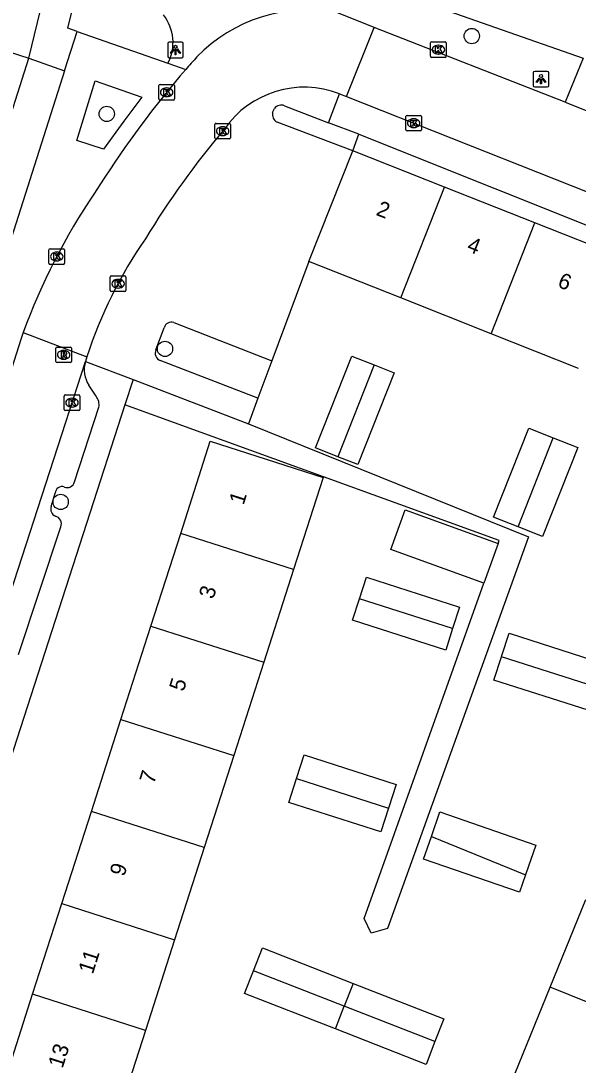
# Model space of a CAD drawing. Extents: x 162812 to 163818, y 381639 to 382470.
# Drawn here: x 163241.1 to 163276.7, y 382068.4 to 382135.2 of the extents above; entities that cross this region are included whole.
import ezdxf

# ---------------------------------------------------------------- set-up
doc = ezdxf.new("R2010")
doc.units = 0
for name, color, linetype in [('IMGEO_Boom', 7, 'Continuous'), ('IMGEO_Groenvoorziening', 7, 'Continuous'), ('IMGEO_Kolk', 7, 'Continuous'), ('IMGEO_Lichtpunt', 7, 'Continuous'), ('IMGEO_Pand', 7, 'Continuous'), ('IMGEO_Pand_nummerreeks', 7, 'Continuous'), ('IMGEO_Parkeervlak_open', 7, 'Continuous'), ('IMGEO_Rijbaan_lokaal_open', 7, 'Continuous'), ('IMGEO_Rioolput', 7, 'Continuous'), ('IMGEO_Voetpad_open', 7, 'Continuous')]:
    doc.layers.add(name, color=color, linetype=linetype)

msp = doc.modelspace()

# ---------------------------------------------------------------- linework, layer by layer
at = {"layer": 'IMGEO_Boom'}
for centre in [(163269.925, 382134.237), (163246.606, 382129.258), (163250.325, 382114.233), (163243.659, 382104.451)]:
    msp.add_circle(centre, 0.489, dxfattribs=at)
at = {"layer": 'IMGEO_Groenvoorziening'}
for points in [[(163262.321, 382126.907), (163262.701, 382127.953)], [(163257.147, 382113.465), (163256.257, 382111.077)]]:
    msp.add_lwpolyline(points, dxfattribs=at)
at = {"layer": 'IMGEO_Kolk'}
for p, q in [((163267.295, 382132.939), (163267.295, 382133.791)), ((163267.37, 382133.865), (163268.222, 382133.865)), ((163267.783, 382133.645), (163267.808, 382133.645)), ((163268.296, 382133.791), (163268.296, 382132.939)), ((163268.222, 382132.865), (163267.37, 382132.865)), ((163267.806, 382133.085), (163267.781, 382133.085)), ((163249.933, 382130.216), (163249.933, 382131.068)), ((163250.008, 382131.142), (163250.86, 382131.142)), ((163250.421, 382130.922), (163250.446, 382130.922)), ((163250.934, 382131.068), (163250.934, 382130.216)), ((163250.86, 382130.142), (163250.008, 382130.142)), ((163250.444, 382130.362), (163250.419, 382130.362)), ((163253.585, 382128.655), (163254.437, 382128.655)), ((163265.715, 382128.24), (163265.715, 382129.092)), ((163265.79, 382129.166), (163266.642, 382129.166)), ((163266.203, 382128.946), (163266.228, 382128.946)), ((163266.716, 382129.092), (163266.716, 382128.24)), ((163253.51, 382127.729), (163253.51, 382128.581)), ((163253.998, 382128.435), (163254.023, 382128.435)), ((163254.511, 382128.581), (163254.511, 382127.729)), ((163266.642, 382128.166), (163265.79, 382128.166)), ((163266.226, 382128.386), (163266.201, 382128.386)), ((163254.437, 382127.655), (163253.585, 382127.655)), ((163254.021, 382127.875), (163253.996, 382127.875)), ((163242.986, 382120.64), (163243.838, 382120.64)), ((163242.911, 382119.714), (163242.911, 382120.566)), ((163243.399, 382120.42), (163243.424, 382120.42)), ((163243.912, 382120.566), (163243.912, 382119.714)), ((163243.838, 382119.64), (163242.986, 382119.64)), ((163243.422, 382119.86), (163243.397, 382119.86)), ((163246.83, 382117.975), (163246.83, 382118.827)), ((163246.905, 382118.901), (163247.757, 382118.901)), ((163247.318, 382118.681), (163247.343, 382118.681)), ((163247.831, 382118.827), (163247.831, 382117.975)), ((163247.341, 382118.121), (163247.316, 382118.121)), ((163247.757, 382117.901), (163246.905, 382117.901)), ((163243.961, 382111.295), (163244.813, 382111.295)), ((163243.886, 382110.369), (163243.886, 382111.221)), ((163244.374, 382111.075), (163244.399, 382111.075)), ((163244.887, 382111.221), (163244.887, 382110.369)), ((163244.813, 382110.295), (163243.961, 382110.295)), ((163244.397, 382110.515), (163244.372, 382110.515))]:
    msp.add_line(p, q, dxfattribs=at)
for points in [[(163267.295, 382132.939), (163267.295, 382133.791)], [(163267.37, 382133.865), (163268.222, 382133.865)], [(163267.616, 382133.565), (163267.739, 382133.565), (163267.739, 382133.414), (163267.869, 382133.565), (163268.033, 382133.565), (163267.887, 382133.414), (163268.04, 382133.165), (163267.888, 382133.165), (163267.803, 382133.329), (163267.739, 382133.262), (163267.739, 382133.165), (163267.616, 382133.165), (163267.616, 382133.565)], [(163268.296, 382133.791), (163268.296, 382132.939)], [(163268.222, 382132.865), (163267.37, 382132.865)], [(163249.933, 382130.216), (163249.933, 382131.068)], [(163250.008, 382131.142), (163250.86, 382131.142)], [(163250.254, 382130.842), (163250.377, 382130.842), (163250.377, 382130.691), (163250.507, 382130.842), (163250.671, 382130.842), (163250.525, 382130.691), (163250.678, 382130.442), (163250.526, 382130.442), (163250.441, 382130.606), (163250.377, 382130.539), (163250.377, 382130.442), (163250.254, 382130.442), (163250.254, 382130.842)], [(163250.934, 382131.068), (163250.934, 382130.216)], [(163250.86, 382130.142), (163250.008, 382130.142)], [(163253.585, 382128.655), (163254.437, 382128.655)], [(163265.715, 382128.24), (163265.715, 382129.092)], [(163265.79, 382129.166), (163266.642, 382129.166)], [(163266.036, 382128.866), (163266.159, 382128.866), (163266.159, 382128.715), (163266.289, 382128.866), (163266.453, 382128.866), (163266.307, 382128.715), (163266.46, 382128.466), (163266.308, 382128.466), (163266.223, 382128.63), (163266.159, 382128.563), (163266.159, 382128.466), (163266.036, 382128.466), (163266.036, 382128.866)], [(163266.716, 382129.092), (163266.716, 382128.24)], [(163253.51, 382127.729), (163253.51, 382128.581)], [(163253.831, 382128.355), (163253.954, 382128.355), (163253.954, 382128.204), (163254.084, 382128.355), (163254.248, 382128.355), (163254.102, 382128.204), (163254.255, 382127.955), (163254.103, 382127.955), (163254.018, 382128.119), (163253.954, 382128.052), (163253.954, 382127.955), (163253.831, 382127.955), (163253.831, 382128.355)], [(163254.511, 382128.581), (163254.511, 382127.729)], [(163266.642, 382128.166), (163265.79, 382128.166)], [(163254.437, 382127.655), (163253.585, 382127.655)], [(163242.986, 382120.64), (163243.838, 382120.64)], [(163242.911, 382119.714), (163242.911, 382120.566)], [(163243.232, 382120.34), (163243.355, 382120.34), (163243.355, 382120.189), (163243.485, 382120.34), (163243.649, 382120.34), (163243.503, 382120.189), (163243.656, 382119.94), (163243.504, 382119.94), (163243.419, 382120.104), (163243.355, 382120.037), (163243.355, 382119.94), (163243.232, 382119.94), (163243.232, 382120.34)], [(163243.912, 382120.566), (163243.912, 382119.714)], [(163243.838, 382119.64), (163242.986, 382119.64)], [(163246.83, 382117.975), (163246.83, 382118.827)], [(163246.905, 382118.901), (163247.757, 382118.901)], [(163247.831, 382118.827), (163247.831, 382117.975)], [(163247.151, 382118.601), (163247.274, 382118.601), (163247.274, 382118.45), (163247.404, 382118.601), (163247.568, 382118.601), (163247.422, 382118.45), (163247.575, 382118.201), (163247.423, 382118.201), (163247.338, 382118.365), (163247.274, 382118.298), (163247.274, 382118.201), (163247.151, 382118.201), (163247.151, 382118.601)], [(163247.757, 382117.901), (163246.905, 382117.901)], [(163243.961, 382111.295), (163244.813, 382111.295)], [(163243.886, 382110.369), (163243.886, 382111.221)], [(163244.207, 382110.995), (163244.33, 382110.995), (163244.33, 382110.844), (163244.46, 382110.995), (163244.624, 382110.995), (163244.478, 382110.844), (163244.631, 382110.595), (163244.479, 382110.595), (163244.394, 382110.759), (163244.33, 382110.692), (163244.33, 382110.595), (163244.207, 382110.595), (163244.207, 382110.995)], [(163244.887, 382111.221), (163244.887, 382110.369)], [(163244.813, 382110.295), (163243.961, 382110.295)]]:
    msp.add_lwpolyline(points, dxfattribs=at)
for centre, start, end in [((163267.372, 382133.789), 91.55205, 178.44795), ((163267.372, 382133.789), 91.55205, 178.44795), ((163268.22, 382133.789), 1.55205, 88.44795), ((163268.22, 382133.789), 1.55205, 88.44795), ((163267.372, 382132.941), 181.55205, 268.44795), ((163267.372, 382132.941), 181.55205, 268.44795), ((163268.22, 382132.941), 271.55205, 358.44795), ((163268.22, 382132.941), 271.55205, 358.44795), ((163250.01, 382131.066), 91.55205, 178.44795), ((163250.01, 382131.066), 91.55205, 178.44795), ((163250.858, 382131.066), 1.55205, 88.44795), ((163250.858, 382131.066), 1.55205, 88.44795), ((163250.01, 382130.218), 181.55205, 268.44795), ((163250.01, 382130.218), 181.55205, 268.44795), ((163250.858, 382130.218), 271.55205, 358.44795), ((163250.858, 382130.218), 271.55205, 358.44795), ((163253.587, 382128.579), 91.55205, 178.44795), ((163253.587, 382128.579), 91.55205, 178.44795), ((163254.435, 382128.579), 1.55205, 88.44795), ((163254.435, 382128.579), 1.55205, 88.44795), ((163265.792, 382129.09), 91.55205, 178.44795), ((163265.792, 382129.09), 91.55205, 178.44795), ((163266.64, 382129.09), 1.55205, 88.44795), ((163266.64, 382129.09), 1.55205, 88.44795), ((163265.792, 382128.242), 181.55205, 268.44795), ((163265.792, 382128.242), 181.55205, 268.44795), ((163266.64, 382128.242), 271.55205, 358.44795), ((163266.64, 382128.242), 271.55205, 358.44795), ((163253.587, 382127.731), 181.55205, 268.44795), ((163253.587, 382127.731), 181.55205, 268.44795), ((163254.435, 382127.731), 271.55205, 358.44795), ((163254.435, 382127.731), 271.55205, 358.44795), ((163242.988, 382120.564), 91.55205, 178.44795), ((163242.988, 382120.564), 91.55205, 178.44795), ((163243.836, 382120.564), 1.55205, 88.44795), ((163243.836, 382120.564), 1.55205, 88.44795), ((163242.988, 382119.716), 181.55205, 268.44795), ((163242.988, 382119.716), 181.55205, 268.44795), ((163243.836, 382119.716), 271.55205, 358.44795), ((163243.836, 382119.716), 271.55205, 358.44795), ((163246.907, 382118.825), 91.55205, 178.44795), ((163246.907, 382118.825), 91.55205, 178.44795), ((163247.755, 382118.825), 1.55205, 88.44795), ((163247.755, 382118.825), 1.55205, 88.44795), ((163246.907, 382117.977), 181.55205, 268.44795), ((163246.907, 382117.977), 181.55205, 268.44795), ((163247.755, 382117.977), 271.55205, 358.44795), ((163247.755, 382117.977), 271.55205, 358.44795), ((163243.963, 382111.219), 91.55205, 178.44795), ((163243.963, 382111.219), 91.55205, 178.44795), ((163244.811, 382111.219), 1.55205, 88.44795), ((163244.811, 382111.219), 1.55205, 88.44795), ((163243.963, 382110.371), 181.55205, 268.44795), ((163243.963, 382110.371), 181.55205, 268.44795), ((163244.811, 382110.371), 271.55205, 358.44795), ((163244.811, 382110.371), 271.55205, 358.44795)]:
    msp.add_arc(centre, 0.0765, start, end, dxfattribs=at)
for centre, major_axis, ratio, start_param, end_param in [((163267.782, 382133.365), (-0.387, 0.002), 0.722429, 4.712389, 7.853982), ((163267.807, 382133.365), (-0.39, 0.002), 0.717154, 1.570796, 4.712389), ((163250.42, 382130.642), (-0.387, 0.002), 0.722429, 4.712389, 7.853982), ((163250.445, 382130.642), (-0.39, 0.002), 0.717154, 1.570796, 4.712389), ((163266.202, 382128.666), (-0.387, 0.002), 0.722429, 4.712389, 7.853982), ((163266.227, 382128.666), (-0.39, 0.002), 0.717154, 1.570796, 4.712389), ((163253.997, 382128.155), (-0.387, 0.002), 0.722429, 4.712389, 7.853982), ((163254.022, 382128.155), (-0.39, 0.002), 0.717154, 1.570796, 4.712389), ((163243.398, 382120.14), (-0.387, 0.002), 0.722429, 4.712389, 7.853982), ((163243.423, 382120.14), (-0.39, 0.002), 0.717154, 1.570796, 4.712389), ((163247.317, 382118.401), (-0.387, 0.002), 0.722429, 4.712389, 7.853982), ((163247.342, 382118.401), (-0.39, 0.002), 0.717154, 1.570796, 4.712389), ((163244.373, 382110.795), (-0.387, 0.002), 0.722429, 4.712389, 7.853982), ((163244.398, 382110.795), (-0.39, 0.002), 0.717154, 1.570796, 4.712389)]:
    msp.add_ellipse(centre, major_axis=major_axis, ratio=ratio, start_param=start_param, end_param=end_param, dxfattribs=at)
at = {"layer": 'IMGEO_Lichtpunt'}
for p, q in [((163250.499, 382133.749), (163250.499, 382132.942)), ((163250.499, 382133.749), (163250.499, 382132.942)), ((163251.401, 382133.844), (163250.593, 382133.844)), ((163251.401, 382133.844), (163250.593, 382133.844)), ((163251.495, 382132.942), (163251.495, 382133.749)), ((163251.495, 382132.942), (163251.495, 382133.749)), ((163250.593, 382132.848), (163251.401, 382132.848)), ((163250.593, 382132.848), (163251.401, 382132.848)), ((163274.753, 382131.978), (163273.945, 382131.978)), ((163274.753, 382131.978), (163273.945, 382131.978)), ((163273.851, 382131.883), (163273.851, 382131.076)), ((163273.851, 382131.883), (163273.851, 382131.076)), ((163274.847, 382131.076), (163274.847, 382131.883)), ((163274.847, 382131.076), (163274.847, 382131.883)), ((163273.945, 382130.982), (163274.753, 382130.982)), ((163273.945, 382130.982), (163274.753, 382130.982))]:
    msp.add_line(p, q, dxfattribs=at)
for points in [[(163250.873, 382133.413), (163250.912, 382133.385), (163250.724, 382133.123), (163250.686, 382133.15), (163250.873, 382133.413)], [(163250.975, 382133.365), (163251.022, 382133.365), (163251.022, 382133.043), (163250.975, 382133.043), (163250.975, 382133.365)], [(163251.085, 382133.385), (163251.123, 382133.412), (163251.31, 382133.15), (163251.271, 382133.122), (163251.085, 382133.385)], [(163274.225, 382131.547), (163274.264, 382131.519), (163274.076, 382131.257), (163274.038, 382131.284), (163274.225, 382131.547)], [(163274.327, 382131.499), (163274.374, 382131.499), (163274.374, 382131.177), (163274.327, 382131.177), (163274.327, 382131.499)], [(163274.437, 382131.519), (163274.475, 382131.546), (163274.662, 382131.284), (163274.623, 382131.256), (163274.437, 382131.519)]]:
    msp.add_lwpolyline(points, dxfattribs=at)
for centre in [(163250.998, 382133.547), (163274.35, 382131.681)]:
    msp.add_circle(centre, 0.0994, dxfattribs=at)
for centre, start, end in [((163250.593, 382133.749), 90, 180), ((163250.593, 382133.749), 90, 180), ((163251.401, 382133.749), 0, 90), ((163251.401, 382133.749), 0, 90), ((163250.593, 382132.942), 180, 270), ((163250.593, 382132.942), 180, 270), ((163251.401, 382132.942), 270, 0), ((163251.401, 382132.942), 270, 360), ((163273.945, 382131.883), 90, 180), ((163273.945, 382131.883), 90, 180), ((163274.753, 382131.883), 0, 90), ((163274.753, 382131.883), 0, 90), ((163273.945, 382131.076), 180, 270), ((163273.945, 382131.076), 180, 270), ((163274.753, 382131.076), 270, 0), ((163274.753, 382131.076), 270, 360)]:
    msp.add_arc(centre, 0.0946, start, end, dxfattribs=at)
at = {"layer": 'IMGEO_Pand'}
for points in [[(163232.729, 382129.228), (163234.599, 382135.074), (163241.617, 382132.829)], [(163239.747, 382126.984), (163241.617, 382132.829)], [(163259.513, 382119.815), (163262.321, 382126.907)], [(163268.194, 382124.581), (163262.321, 382126.907)], [(163265.386, 382117.489), (163268.194, 382124.581)], [(163273.965, 382122.295), (163268.194, 382124.581)], [(163271.157, 382115.203), (163273.965, 382122.295)], [(163279.552, 382120.082), (163273.965, 382122.295)], [(163265.386, 382117.489), (163259.513, 382119.815)], [(163271.157, 382115.203), (163265.386, 382117.489)], [(163276.744, 382112.991), (163271.157, 382115.203)], [(163261.369, 382107.344), (163259.934, 382107.912), (163262.258, 382113.779), (163263.692, 382113.211)], [(163263.692, 382113.211), (163264.977, 382112.703), (163262.653, 382106.835), (163261.369, 382107.344)], [(163263.692, 382113.211), (163261.369, 382107.344)], [(163272.886, 382102.865), (163271.325, 382103.483), (163273.573, 382109.161), (163275.135, 382108.543)], [(163251.328, 382102.438), (163253.218, 382108.325), (163257.979, 382106.798), (163260.423, 382106.012), (163258.533, 382100.124)], [(163275.135, 382108.543), (163276.696, 382107.925), (163274.448, 382102.246), (163272.886, 382102.865)], [(163272.886, 382102.865), (163275.135, 382108.543)], [(163270.692, 382099.257), (163264.753, 382101.415), (163265.671, 382103.942), (163271.61, 382101.784)], [(163249.427, 382096.517), (163251.328, 382102.438)], [(163258.533, 382100.124), (163251.328, 382102.438)], [(163271.61, 382101.784), (163270.692, 382099.257)], [(163258.533, 382100.124), (163256.632, 382094.203)], [(163262.75, 382098.266), (163263.19, 382099.637), (163269.143, 382097.725), (163268.703, 382096.354)], [(163268.703, 382096.354), (163268.263, 382094.983), (163262.309, 382096.894), (163262.75, 382098.266)], [(163268.703, 382096.354), (163262.75, 382098.266)], [(163247.511, 382090.551), (163249.427, 382096.517)], [(163249.427, 382096.517), (163256.632, 382094.203)], [(163271.827, 382094.558), (163271.85, 382094.628), (163272.309, 382096.058), (163278.319, 382094.128), (163277.837, 382092.629)], [(163256.632, 382094.203), (163254.716, 382088.237)], [(163277.837, 382092.629), (163277.356, 382091.13), (163271.346, 382093.059), (163271.827, 382094.558)], [(163277.837, 382092.629), (163271.827, 382094.558)], [(163245.622, 382084.665), (163247.511, 382090.551)], [(163247.511, 382090.551), (163254.716, 382088.237)], [(163254.716, 382088.237), (163252.826, 382082.351)], [(163258.726, 382086.763), (163259.213, 382088.282), (163265.086, 382086.396), (163264.598, 382084.878)], [(163264.598, 382084.878), (163264.111, 382083.359), (163258.238, 382085.245), (163258.726, 382086.763)], [(163258.726, 382086.763), (163264.598, 382084.878)], [(163243.731, 382078.775), (163245.622, 382084.665)], [(163252.826, 382082.351), (163245.622, 382084.665)], [(163267.35, 382083.057), (163267.894, 382084.632), (163274.023, 382082.514), (163273.365, 382080.61)], [(163273.365, 382080.61), (163272.98, 382079.498), (163266.852, 382081.617), (163267.35, 382083.057)], [(163267.35, 382083.057), (163273.365, 382080.61)], [(163252.826, 382082.351), (163250.936, 382076.462)], [(163241.867, 382072.971), (163243.731, 382078.775)], [(163243.731, 382078.775), (163250.936, 382076.462)], [(163274.938, 382073.436), (163277.218, 382079.042)], [(163250.936, 382076.462), (163249.072, 382070.658)], [(163255.982, 382074.483), (163256.552, 382075.94), (163262.349, 382073.673)], [(163261.209, 382070.759), (163255.412, 382073.025), (163255.982, 382074.483)], [(163261.779, 382072.216), (163255.982, 382074.483)], [(163262.349, 382073.673), (163261.779, 382072.216)], [(163262.349, 382073.673), (163268.146, 382071.406), (163267.576, 382069.949)], [(163272.7, 382067.933), (163274.938, 382073.436)], [(163281.998, 382070.565), (163274.938, 382073.436)], [(163239.976, 382067.082), (163241.867, 382072.971)], [(163249.072, 382070.658), (163241.867, 382072.971)], [(163261.209, 382070.759), (163261.779, 382072.216)], [(163267.576, 382069.949), (163261.779, 382072.216)], [(163249.072, 382070.658), (163247.181, 382064.768)], [(163267.576, 382069.949), (163267.007, 382068.492), (163261.209, 382070.759)]]:
    msp.add_lwpolyline(points, dxfattribs=at)
at = {"layer": 'IMGEO_Parkeervlak_open'}
for points in [[(163257.201, 382129.354), (163257.313, 382129.601)], [(163257.971, 382129.781), (163260.781, 382128.695)], [(163262.321, 382126.907), (163257.492, 382128.73)], [(163259.513, 382119.815), (163257.147, 382113.465)], [(163249.745, 382114.171), (163250.277, 382115.589)], [(163250.885, 382115.912), (163257.147, 382113.465)], [(163256.257, 382111.077), (163250.026, 382113.484)], [(163256.257, 382111.077), (163255.652, 382109.452)]]:
    msp.add_lwpolyline(points, dxfattribs=at)
for centre, radius, start, end in [((163257.75, 382129.23), 0.562, 167.26541, 242.73822), ((163257.755, 382129.277), 0.548, 66.80198, 143.79665), ((163250.721, 382115.487), 0.456, 68.93761, 167.02134), ((163250.205, 382113.958), 0.507, 155.17146, 249.32009)]:
    msp.add_arc(centre, radius, start, end, dxfattribs=at)
at = {"layer": 'IMGEO_Rijbaan_lokaal_open'}
for points in [[(163263.682, 382134.785), (163261.304, 382135.746)], [(163261.931, 382130.364), (163263.682, 382134.785)], [(163275.884, 382130.001), (163263.682, 382134.785)], [(163261.477, 382130.544), (163261.931, 382130.364)], [(163261.931, 382130.364), (163281.92, 382122.447)], [(163275.884, 382130.001), (163279.33, 382128.645)], [(163241.478, 382115.855), (163241.269, 382115.279)], [(163241.269, 382115.279), (163241.135, 382114.908), (163233.288, 382090.334)], [(163241.269, 382115.279), (163245.337, 382113.722)], [(163238.39, 382092.328), (163245.241, 382113.426)], [(163245.337, 382113.722), (163245.241, 382113.426)]]:
    msp.add_lwpolyline(points, dxfattribs=at)
for centre, radius, start, end in [((163259.485, 382125.988), 9.926, 79.44108, 135.85705), ((163312.227, 382079.546), 80.191, 138.29063, 139.0556), ((163299.203, 382091.012), 62.839, 139.17024, 147.55871), ((163259.229, 382124.755), 6.21, 68.77537, 145.28109), ((163296.551, 382092.445), 55.543, 139.80475, 148.72837), ((163281.347, 382100.43), 42.749, 145.37398, 158.84929), ((163273.086, 382104.688), 29.183, 145.35832, 161.96751)]:
    msp.add_arc(centre, radius, start, end, dxfattribs=at)
at = {"layer": 'IMGEO_Rioolput'}
for p, q in [((163243.352, 382113.429), (163243.352, 382114.281)), ((163243.427, 382114.355), (163244.279, 382114.355)), ((163243.84, 382114.135), (163243.865, 382114.135)), ((163244.353, 382114.281), (163244.353, 382113.429)), ((163244.279, 382113.355), (163243.427, 382113.355)), ((163243.863, 382113.575), (163243.838, 382113.575))]:
    msp.add_line(p, q, dxfattribs=at)
for points in [[(163243.352, 382113.429), (163243.352, 382114.281)], [(163243.427, 382114.355), (163244.279, 382114.355)], [(163243.941, 382114.053), (163243.689, 382114.055), (163243.689, 382113.655)], [(163243.867, 382113.974), (163243.813, 382113.974), (163243.813, 382113.893)], [(163244.353, 382114.281), (163244.353, 382113.429)], [(163244.279, 382113.355), (163243.427, 382113.355)], [(163243.689, 382113.655), (163243.813, 382113.655), (163243.813, 382113.817), (163243.824, 382113.817)], [(163243.813, 382113.893), (163243.865, 382113.893)], [(163243.871, 382113.788), (163243.942, 382113.655), (163244.082, 382113.655), (163244.017, 382113.781)]]:
    msp.add_lwpolyline(points, dxfattribs=at)
for centre, radius, start, end in [((163243.429, 382114.279), 0.0765, 91.55205, 178.44795), ((163243.429, 382114.279), 0.0765, 91.55205, 178.44795), ((163243.873, 382113.878), 0.0964, 77.00612, 93.18647), ((163243.887, 382113.935), 0.0378, 276.66336, 79.67722), ((163243.94, 382113.943), 0.109, 350.36119, 89.41601), ((163244.277, 382114.279), 0.0765, 1.55205, 88.44795), ((163244.277, 382114.279), 0.0765, 1.55205, 88.44795), ((163243.429, 382113.431), 0.0765, 181.55205, 268.44795), ((163243.429, 382113.431), 0.0765, 181.55205, 268.44795), ((163243.823, 382113.764), 0.0533, 26.02933, 88.69889), ((163243.849, 382114.082), 0.19, 274.7715, 282.96867), ((163243.938, 382113.943), 0.112, 277.58423, 350.98172), ((163243.922, 382113.728), 0.108, 29.51342, 73.79051), ((163244.277, 382113.431), 0.0765, 271.55205, 358.44795), ((163244.277, 382113.431), 0.0765, 271.55205, 358.44795)]:
    msp.add_arc(centre, radius, start, end, dxfattribs=at)
for centre, major_axis, ratio, start_param, end_param in [((163243.839, 382113.855), (-0.387, 0.002), 0.722429, 4.712389, 7.853982), ((163243.864, 382113.855), (-0.39, 0.002), 0.717154, 1.570796, 4.712389)]:
    msp.add_ellipse(centre, major_axis=major_axis, ratio=ratio, start_param=start_param, end_param=end_param, dxfattribs=at)
at = {"layer": 'IMGEO_Voetpad_open'}
for points in [[(163241.617, 382132.829), (163244.749, 382145.727), (163244.795, 382145.935)], [(163261.304, 382135.746), (163257.303, 382136.866), (163251.788, 382138.414), (163250.622, 382141.369), (163262.733, 382138.041), (163265.845, 382136.765), (163277.044, 382132.812), (163275.884, 382130.001)], [(163244.712, 382134.536), (163244.11, 382134.746), (163245.309, 382139.637)], [(163243.91, 382132.016), (163244.712, 382134.536)], [(163244.712, 382134.536), (163250.515, 382132.508)], [(163241.617, 382132.829), (163243.91, 382132.016)], [(163243.91, 382132.016), (163230.592, 382090.193)], [(163250.515, 382132.508), (163251.655, 382132.097)], [(163248.853, 382130.33), (163247.697, 382128.792), (163246.4, 382127.007), (163244.689, 382127.558), (163245.873, 382131.37), (163248.853, 382130.33)], [(163260.781, 382128.695), (163261.477, 382130.544)], [(163262.701, 382127.953), (163260.781, 382128.695)], [(163262.701, 382127.953), (163297.458, 382114.069)], [(163245.241, 382113.426), (163248.285, 382112.285)], [(163248.285, 382112.285), (163247.759, 382110.658)], [(163248.285, 382112.285), (163255.652, 382109.452)], [(163245.918, 382111.21), (163245.464, 382111.922)], [(163247.759, 382110.658), (163228.176, 382050.033), (163230.013, 382049.41), (163229.849, 382048.901)], [(163271.61, 382101.784), (163271.679, 382101.987), (163247.759, 382110.658)], [(163244.548, 382105.727), (163246.106, 382110.509)], [(163255.652, 382109.452), (163273.542, 382102.209), (163264.542, 382077.185), (163263.496, 382076.874), (163263.061, 382077.818), (163270.692, 382099.257)], [(163243.056, 382104.157), (163243.31, 382105.01)], [(163240.968, 382094.694), (163243.666, 382102.869)]]:
    msp.add_lwpolyline(points, dxfattribs=at)
for centre, radius, start, end in [((163248.011, 382133.825), 2.829, 332.25724, 38.37701), ((163246.936, 382112.909), 1.772, 163.03237, 213.83537), ((163245.252, 382110.656), 0.866, 350.24399, 39.78157), ((163243.741, 382105), 0.431, 68.89654, 178.66391), ((163244.075, 382105.86), 0.492, 248.68726, 344.30216), ((163243.532, 382103.992), 0.504, 160.91842, 245.47876), ((163243.223, 382103.061), 0.483, 336.56167, 78.00675)]:
    msp.add_arc(centre, radius, start, end, dxfattribs=at)

# ---------------------------------------------------------------- texts
at = {"layer": 'IMGEO_Pand_nummerreeks'}
for s, rotation, p in [('2', 338.39196, (163263.754, 382122.812)), ('4', 338.39196, (163269.553, 382120.514)), ('6', 338.39196, (163275.351, 382118.218)), ('1', 72.2, (163255.343, 382104.212)), ('3', 72.2, (163253.41, 382098.191)), ('5', 72.2, (163251.512, 382092.279)), ('7', 72.2, (163249.613, 382086.367)), ('9', 72.2, (163247.715, 382080.455)), ('11', 72.2, (163245.711, 382074.213)), ('13', 72.2, (163243.778, 382068.193))]:
    msp.add_text(s, height=1, rotation=rotation, dxfattribs=at).set_placement(p)

doc.saveas('drawing.dxf')
